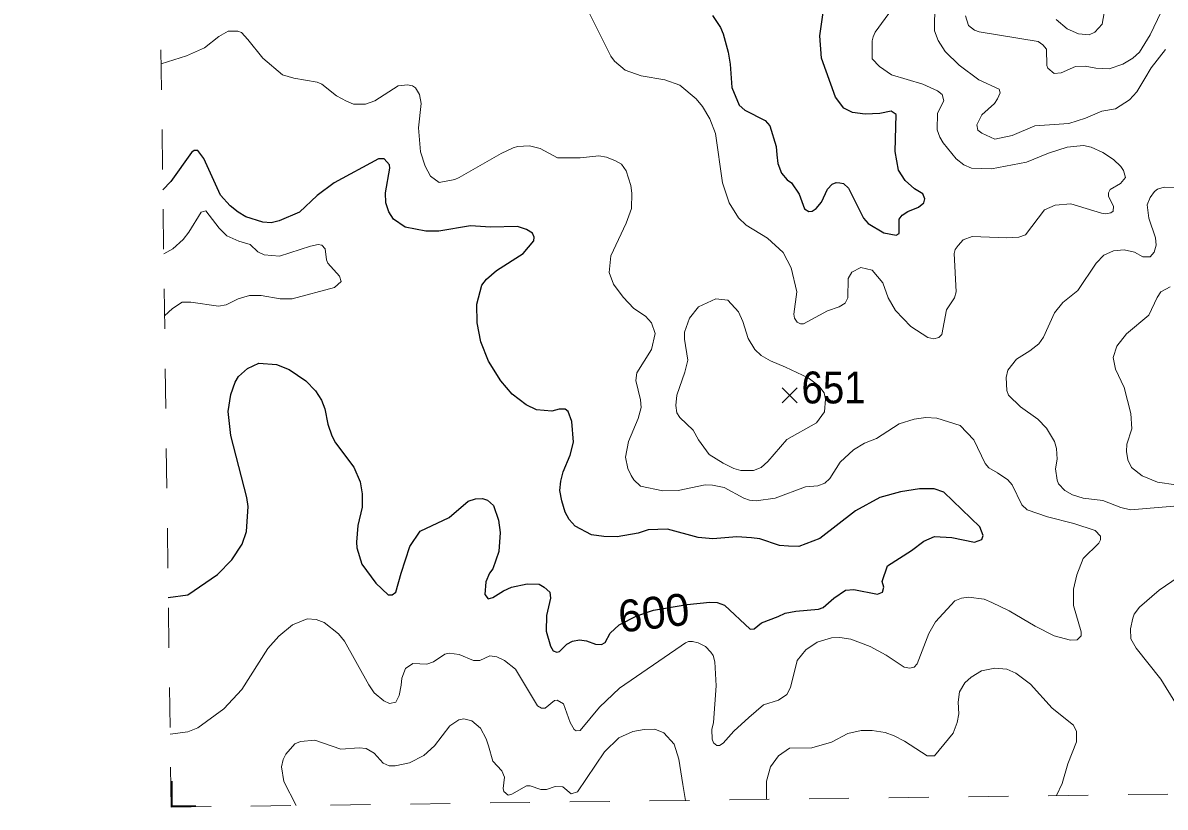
# Model space of a CAD drawing. Extents: x 294.2 to 320.3, y 7482.7 to 7510.7.
# Drawn here: x 294.252 to 297.116, y 7482.735 to 7484.703 of the extents above; entities that cross this region are included whole.
import ezdxf
from ezdxf.enums import TextEntityAlignment as Align

# ---------------------------------------------------------------- set-up
doc = ezdxf.new("R2010")
doc.units = 0
doc.header["$LTSCALE"] = 0.032
doc.linetypes.add('SHORT_DASHED', pattern=[2.7, 1.5, -1.2])
for name, color, linetype, lineweight in [('1', 7, 'Continuous', 25), ('2', 7, 'Continuous', 13), ('21', 7, 'Continuous', 25), ('22', 7, 'SHORT_DASHED', 13), ('63', 7, 'Continuous', 25)]:
    doc.layers.add(name, color=color, linetype=linetype, lineweight=lineweight)
doc.layers.add('61', color=7, linetype='Continuous')

msp = doc.modelspace()

# ---------------------------------------------------------------- linework, layer by layer
at = {"layer": '1'}
for points in [[(295.9814, 7484.7214), (296.0012, 7484.6908), (296.0076, 7484.6755), (296.0204, 7484.6295), (296.0255, 7484.5988), (296.0294, 7484.5404), (296.048, 7484.4963), (296.0619, 7484.4839), (296.1129, 7484.4575), (296.1245, 7484.4441), (296.1409, 7484.3925), (296.142, 7484.3715), (296.1451, 7484.35), (296.1542, 7484.3258), (296.1686, 7484.3093), (296.1789, 7484.3016), (296.198, 7484.2727), (296.2117, 7484.236), (296.2228, 7484.2296), (296.2308, 7484.2301), (296.2414, 7484.2371), (296.2547, 7484.2527), (296.2691, 7484.2855), (296.2813, 7484.2984), (296.2913, 7484.3027), (296.3007, 7484.3017), (296.3096, 7484.3), (296.3223, 7484.2885), (296.3594, 7484.2125), (296.3715, 7484.1997), (296.4111, 7484.1761), (296.4417, 7484.1698), (296.4488, 7484.1742), (296.4494, 7484.21), (296.4564, 7484.2202), (296.4711, 7484.2298), (296.4973, 7484.2406), (296.5113, 7484.2515), (296.5139, 7484.2611), (296.5088, 7484.2738), (296.4877, 7484.2866), (296.4641, 7484.3077), (296.4475, 7484.3332), (296.4392, 7484.3805), (296.4417, 7484.4731), (296.429, 7484.4814), (296.4009, 7484.4756), (296.3639, 7484.4737), (296.3319, 7484.4781), (296.3102, 7484.489), (296.2898, 7484.5165), (296.254, 7484.6142), (296.2502, 7484.6703), (296.2623, 7484.7521)], [(296.5375, 7483.4144), (296.5809, 7483.4119), (296.6378, 7483.4004), (296.6563, 7483.4068), (296.6601, 7483.4164), (296.6518, 7483.4387), (296.5611, 7483.5255), (296.5373, 7483.5338), (296.5006, 7483.5338), (296.4527, 7483.5263), (296.4011, 7483.5123), (296.34, 7483.4784), (296.25, 7483.4089), (296.1975, 7483.3895), (296.172, 7483.3901), (296.1493, 7483.3914), (296.0995, 7483.4087), (296.0791, 7483.4113), (296.0421, 7483.4132), (295.9821, 7483.4087), (295.945, 7483.4119), (295.8684, 7483.433), (295.8199, 7483.431), (295.7943, 7483.4228), (295.7419, 7483.4138), (295.7086, 7483.4143), (295.6773, 7483.4187), (295.6368, 7483.4402), (295.6213, 7483.4569), (295.6113, 7483.4752), (295.603, 7483.5037), (295.5985, 7483.5296), (295.601, 7483.5533), (295.6065, 7483.5764), (295.6245, 7483.6181), (295.6322, 7483.6513), (295.6283, 7483.7024), (295.6194, 7483.7279), (295.6117, 7483.7337), (295.5964, 7483.7337), (295.5785, 7483.7286), (295.5396, 7483.7318), (295.5134, 7483.7445), (295.4789, 7483.7714), (295.4502, 7483.8045), (295.4195, 7483.8544), (295.4004, 7483.9029), (295.3908, 7483.9501), (295.3902, 7483.9974), (295.4029, 7484.0446), (295.4144, 7484.06), (295.4394, 7484.0817), (295.5064, 7484.1238), (295.5326, 7484.1563), (295.5338, 7484.1653), (295.5294, 7484.1755), (295.5144, 7484.1846), (295.4922, 7484.1916), (295.4239, 7484.1906), (295.374, 7484.1938), (295.2944, 7484.1804), (295.2625, 7484.1804), (295.2104, 7484.1906), (295.1807, 7484.2105), (295.1696, 7484.2288), (295.1619, 7484.2514), (295.1613, 7484.2761), (295.1721, 7484.3379), (295.1712, 7484.3466), (295.1578, 7484.3619), (295.1437, 7484.3613), (295.0324, 7484.3011), (294.9897, 7484.2693), (294.9456, 7484.2279), (294.8946, 7484.2063), (294.8746, 7484.2015), (294.8532, 7484.2031), (294.8111, 7484.2166), (294.7911, 7484.2279), (294.7712, 7484.244), (294.7472, 7484.2706), (294.7051, 7484.3626), (294.6904, 7484.3823), (294.6808, 7484.3823), (294.6745, 7484.3773), (294.6223, 7484.3052), (294.6026, 7484.2836)], [(294.6163, 7483.261), (294.6652, 7483.2683), (294.7395, 7483.3187), (294.7753, 7483.3554), (294.8015, 7483.3947), (294.8122, 7483.4267), (294.8162, 7483.4898), (294.8136, 7483.5122), (294.7728, 7483.6679), (294.7664, 7483.728), (294.7728, 7483.7701), (294.7842, 7483.8014), (294.7926, 7483.8154), (294.8149, 7483.8358), (294.843, 7483.8493), (294.8877, 7483.8454), (294.919, 7483.8333), (294.9611, 7483.8046), (294.9853, 7483.7796), (295.0002, 7483.756), (295.0091, 7483.7345), (295.0162, 7483.6963), (295.0262, 7483.6666), (295.0352, 7483.6494), (295.0818, 7483.5881), (295.0971, 7483.5517), (295.1022, 7483.5211), (295.1022, 7483.4878), (295.0914, 7483.4419), (295.0882, 7483.3998), (295.0888, 7483.3857), (295.1016, 7483.3449), (295.1367, 7483.2976), (295.1673, 7483.2676), (295.1776, 7483.2676), (295.1871, 7483.2746), (295.1999, 7483.3219), (295.2223, 7483.3896), (295.2478, 7483.4278), (295.3207, 7483.4622), (295.3684, 7483.5031), (295.3867, 7483.5085), (295.4039, 7483.5095), (295.4172, 7483.5058), (295.4317, 7483.4918), (295.4447, 7483.4552), (295.4486, 7483.4245), (295.4451, 7483.3768), (295.4298, 7483.3333), (295.4214, 7483.3219), (295.4125, 7483.3002), (295.4105, 7483.2685), (295.4182, 7483.2583), (295.4304, 7483.261), (295.4565, 7483.2782), (295.477, 7483.2868), (295.516, 7483.2956), (295.5465, 7483.2945), (295.5587, 7483.287), (295.5731, 7483.2746), (295.5748, 7483.2596), (295.5647, 7483.2162), (295.5636, 7483.1764), (295.5747, 7483.1393), (295.5816, 7483.1275), (295.5905, 7483.1242), (295.5977, 7483.1259), (295.616, 7483.1441), (295.6299, 7483.1517), (295.6471, 7483.1554), (295.6654, 7483.1527), (295.6873, 7483.1446), (295.7023, 7483.1436), (295.7117, 7483.1484), (295.7245, 7483.1715), (295.7472, 7483.1925), (295.7913, 7483.2151), (295.8329, 7483.2291), (295.9175, 7483.2436), (295.9747, 7483.2496), (295.9925, 7483.249), (296.0114, 7483.2421), (296.0753, 7483.182), (296.0855, 7483.1827), (296.104, 7483.198), (296.1455, 7483.2139), (296.1637, 7483.2219), (296.1904, 7483.2273), (296.2469, 7483.2322), (296.2586, 7483.236), (296.2852, 7483.2596), (296.3146, 7483.2796), (296.3357, 7483.2812), (296.395, 7483.2698), (296.4072, 7483.2746)], [(296.4072, 7483.2746), (296.4105, 7483.287), (296.4067, 7483.3015), (296.42, 7483.3408), (296.4805, 7483.3789), (296.5113, 7483.4023), (296.5375, 7483.4144)]]:
    msp.add_lwpolyline(points, dxfattribs=at)
at = {"layer": '2'}
for points in [[(296.0063, 7484.3013), (296.0229, 7484.2515), (296.0459, 7484.2138), (296.0657, 7484.1953), (296.1193, 7484.1628), (296.1582, 7484.1264), (296.1787, 7484.0881), (296.1927, 7484.028), (296.185, 7483.9719), (296.1863, 7483.9616), (296.1934, 7483.9521), (296.2017, 7483.9475), (296.2093, 7483.9475), (296.2694, 7483.9801), (296.2987, 7483.9904), (296.3141, 7483.9999), (296.3204, 7484.0127), (296.3217, 7484.0612), (296.3306, 7484.0772), (296.353, 7484.0887), (296.3817, 7484.0823), (296.4085, 7484.051), (296.422, 7484.0127), (296.4404, 7483.9814), (296.4781, 7483.9412), (296.5209, 7483.9131), (296.5363, 7483.9105), (296.549, 7483.9131), (296.556, 7483.9208), (296.5675, 7483.9833), (296.588, 7484.0133), (296.5924, 7484.028), (296.5873, 7484.1238), (296.5898, 7484.134), (296.5969, 7484.1442), (296.6097, 7484.1589), (296.632, 7484.1666), (296.7189, 7484.1634), (296.7495, 7484.1653), (296.7661, 7484.171), (296.814, 7484.2336), (296.8402, 7484.2451), (296.8798, 7484.2489), (296.9564, 7484.2253), (296.9666, 7484.2234), (296.98, 7484.2259), (296.9857, 7484.2304), (296.987, 7484.2426), (296.9742, 7484.2668), (296.9742, 7484.2764), (296.9781, 7484.2847), (297.0042, 7484.2994), (297.0164, 7484.3147), (297.0119, 7484.3326), (297.0055, 7484.3428), (296.987, 7484.36), (296.9602, 7484.3779), (296.9308, 7484.3913), (296.9117, 7484.3952), (296.8708, 7484.3913), (296.8236, 7484.376), (296.7687, 7484.353), (296.6806, 7484.3364), (296.6308, 7484.3383), (296.6116, 7484.3466), (296.5918, 7484.3613), (296.5599, 7484.4022), (296.5509, 7484.4162), (296.5445, 7484.4341), (296.5452, 7484.4763), (296.5612, 7484.5075), (296.5573, 7484.5228), (296.5452, 7484.5324), (296.5082, 7484.549), (296.4303, 7484.5727), (296.3996, 7484.5937), (296.3817, 7484.6129), (296.3811, 7484.6575), (296.3843, 7484.6678), (296.3894, 7484.6793), (296.4481, 7484.761)], [(295.6596, 7484.7534), (295.726, 7484.6193), (295.7349, 7484.6071), (295.7624, 7484.5841), (295.802, 7484.5701), (295.8613, 7484.5599)], [(296.5388, 7484.7508), (296.5375, 7484.6831), (296.5471, 7484.6589), (296.5643, 7484.6308), (296.5994, 7484.5963), (296.6486, 7484.5599), (296.7003, 7484.5362), (296.7029, 7484.5273), (296.6958, 7484.512), (296.6882, 7484.5005), (296.6569, 7484.4724), (296.6442, 7484.4469), (296.6467, 7484.4335), (296.6563, 7484.4258), (296.6895, 7484.4111), (296.7329, 7484.42), (296.7891, 7484.4443), (296.8747, 7484.4507), (296.9168, 7484.4634), (296.9577, 7484.4813), (296.9921, 7484.4871), (297.0272, 7484.5094), (297.0451, 7484.5298), (297.0655, 7484.5631), (297.0809, 7484.5899), (297.1172, 7484.6358)], [(296.6154, 7484.7201), (296.623, 7484.6965), (296.6377, 7484.6843), (296.6499, 7484.6805), (296.798, 7484.6563), (296.8095, 7484.648), (296.8184, 7484.6365), (296.8197, 7484.5956), (296.8222, 7484.5892), (296.8376, 7484.5758), (296.8555, 7484.5771), (296.8913, 7484.5937), (296.9155, 7484.5944), (296.9423, 7484.5892), (296.9755, 7484.5873), (297.01, 7484.5988), (297.0355, 7484.6141), (297.0515, 7484.6295), (297.0783, 7484.6729), (297.1153, 7484.7495)], [(296.8427, 7484.7112), (296.8701, 7484.6882), (296.8989, 7484.6754), (296.9257, 7484.6729), (296.9398, 7484.6792), (296.9583, 7484.6997), (296.9634, 7484.7278)], [(294.8156, 7484.6614), (294.7996, 7484.6786), (294.7907, 7484.6818), (294.7664, 7484.6818), (294.7434, 7484.6684), (294.707, 7484.6403), (294.6617, 7484.6199), (294.5984, 7484.5999)], [(296.9538, 7483.4061), (296.9538, 7483.4151), (296.9411, 7483.4291), (296.8874, 7483.447), (296.821, 7483.4636), (296.7699, 7483.4815), (296.7565, 7483.4936), (296.7323, 7483.5441), (296.7214, 7483.5568), (296.6959, 7483.5741), (296.6741, 7483.5868), (296.6646, 7483.597), (296.6365, 7483.6564), (296.602, 7483.6928), (296.5439, 7483.7113), (296.5158, 7483.7126), (296.4865, 7483.7088), (296.4494, 7483.6973), (296.392, 7483.6602), (296.3626, 7483.6481), (296.3345, 7483.6315), (296.3013, 7483.6009), (296.2751, 7483.5594), (296.263, 7483.5479), (296.2451, 7483.5415), (296.2145, 7483.5389), (296.1378, 7483.5108), (296.0906, 7483.5038), (296.074, 7483.5051), (296.06, 7483.5102), (296.0102, 7483.5376), (295.9808, 7483.5428), (295.9629, 7483.544), (295.8952, 7483.53), (295.8569, 7483.5287), (295.8007, 7483.5409), (295.7835, 7483.5562), (295.7771, 7483.5671), (295.7688, 7483.5849), (295.7631, 7483.613), (295.7707, 7483.6526), (295.795, 7483.7101), (295.802, 7483.7382), (295.8007, 7483.7573), (295.7892, 7483.8059), (295.7917, 7483.825), (295.8282, 7483.8837), (295.8371, 7483.9233), (295.8282, 7483.9501), (295.8128, 7483.9674), (295.7835, 7483.9859), (295.7573, 7484.0146), (295.7324, 7484.0472), (295.7215, 7484.0766), (295.726, 7484.118), (295.7643, 7484.2004), (295.7777, 7484.2375), (295.779, 7484.2758), (295.7764, 7484.2949), (295.7643, 7484.332), (295.7528, 7484.3479), (295.7382, 7484.3568), (295.7152, 7484.3658), (295.696, 7484.3689), (295.6488, 7484.3638), (295.5926, 7484.3638), (295.5492, 7484.3875), (295.5224, 7484.3939), (295.4917, 7484.3926), (295.4815, 7484.3894), (295.4508, 7484.3754), (295.3461, 7484.3147), (295.3346, 7484.3096), (295.2957, 7484.3026), (295.274, 7484.3179), (295.2605, 7484.3434), (295.249, 7484.3792), (295.2439, 7484.4392), (295.2503, 7484.5005), (295.2459, 7484.5235), (295.2363, 7484.5395), (295.2286, 7484.5452), (295.2159, 7484.5471), (295.1929, 7484.5452), (295.1342, 7484.5069), (295.1112, 7484.4992), (295.0805, 7484.4986), (295.0633, 7484.5063), (295.0377, 7484.5196), (295.0014, 7484.549), (294.9899, 7484.5541), (294.9311, 7484.5637), (294.903, 7484.5726), (294.8532, 7484.6142), (294.8156, 7484.6614)], [(295.8613, 7484.5599), (295.8991, 7484.5464), (295.9399, 7484.512), (295.9559, 7484.4929), (295.9744, 7484.4622), (295.9884, 7484.4252), (296.0063, 7484.3013)], [(297.1466, 7484.2892), (297.1134, 7484.291), (297.0968, 7484.2853), (297.0898, 7484.2796), (297.0789, 7484.2643), (297.0713, 7484.2464), (297.0751, 7484.2132), (297.0917, 7484.1634), (297.0936, 7484.1455), (297.0885, 7484.1276), (297.0789, 7484.1161), (297.0604, 7484.1161), (297.0394, 7484.1276), (297.0138, 7484.1334), (296.987, 7484.1308), (296.9628, 7484.12), (296.9436, 7484.0996), (296.897, 7484.0318), (296.8593, 7484.0012), (296.8388, 7483.9757), (296.8114, 7483.9144), (296.7993, 7483.8978), (296.7769, 7483.8799), (296.7431, 7483.8595), (296.722, 7483.8314), (296.7175, 7483.8135), (296.7188, 7483.7803), (296.7233, 7483.7688), (296.7533, 7483.7394), (296.7968, 7483.7088), (296.8191, 7483.6864), (296.8388, 7483.6526), (296.844, 7483.6347), (296.8452, 7483.6079), (296.8414, 7483.5837), (296.8452, 7483.5556), (296.8491, 7483.5466), (296.8644, 7483.53), (296.8836, 7483.5185), (296.9104, 7483.5108), (296.9602, 7483.5044), (297.0049, 7483.4872), (297.0292, 7483.4815), (297.1683, 7483.493)], [(294.6048, 7484.123), (294.6278, 7484.1359), (294.6534, 7484.1596), (294.668, 7484.1774), (294.6987, 7484.2279), (294.7102, 7484.231), (294.744, 7484.1876), (294.7632, 7484.1685), (294.7932, 7484.1551), (294.8219, 7484.1468), (294.8411, 7484.1283), (294.8571, 7484.1212), (294.8954, 7484.1174), (294.9733, 7484.1429), (294.9924, 7484.1468), (295.0014, 7484.1455), (295.0097, 7484.1359), (295.0128, 7484.1085), (295.0166, 7484.0996), (295.0454, 7484.0676), (295.0498, 7484.0536), (295.0333, 7484.0389), (294.9273, 7484.0108), (294.8966, 7484.0101), (294.8494, 7484.0191), (294.82, 7484.0191), (294.7919, 7484.0108), (294.7613, 7483.9955), (294.7421, 7483.9922), (294.6732, 7484.0025), (294.6508, 7484.0019), (294.6266, 7483.9865), (294.6068, 7483.9675)], [(297.1287, 7484.0408), (297.1057, 7484.028), (297.0962, 7484.014), (297.0757, 7483.9693), (297.0189, 7483.9227), (296.9953, 7483.8914), (296.9857, 7483.8633), (296.9921, 7483.8339), (297.0138, 7483.788), (297.0304, 7483.7228), (297.0329, 7483.6845), (297.0202, 7483.6462), (297.0189, 7483.6271), (297.0227, 7483.6066), (297.0317, 7483.5874), (297.0585, 7483.5664), (297.0968, 7483.5504), (297.1428, 7483.544)], [(296.9053, 7483.175), (296.8861, 7483.2414), (296.8861, 7483.2823), (296.895, 7483.3181), (296.911, 7483.3589), (296.9499, 7483.3972), (296.9538, 7483.4061)], [(297.1645, 7483.3231), (297.1013, 7483.2797), (297.0521, 7483.237), (297.0387, 7483.2197), (297.0349, 7483.2095), (297.0291, 7483.1827), (297.0298, 7483.1572), (297.0432, 7483.1342), (297.1057, 7483.0563), (297.1434, 7482.995)], [(294.6209, 7482.9187), (294.6655, 7482.9241), (294.6904, 7482.9343), (294.7555, 7482.9816), (294.8008, 7483.0307), (294.866, 7483.1329), (294.8934, 7483.1642), (294.9279, 7483.1929), (294.9649, 7483.2076), (294.9873, 7483.2063), (295.0071, 7483.1987), (295.0429, 7483.1705), (295.0582, 7483.1521), (295.1188, 7483.0422), (295.1328, 7483.0224), (295.1571, 7483.002), (295.1712, 7482.9956), (295.1871, 7482.9988), (295.1954, 7483.0154), (295.2005, 7483.041), (295.2018, 7483.0588), (295.2114, 7483.0831), (295.2293, 7483.0958), (295.2644, 7483.0939), (295.2816, 7483.0996), (295.3097, 7483.1195), (295.3206, 7483.122), (295.3461, 7483.1182), (295.3819, 7483.1035), (295.3972, 7483.1035), (295.4228, 7483.115), (295.4406, 7483.1124), (295.4597, 7483.1029), (295.4872, 7483.0811), (295.5421, 7482.9898), (295.5523, 7482.9834), (295.5613, 7482.9834), (295.5849, 7483.0026), (295.5913, 7483.0039), (295.6073, 7482.9943), (295.6245, 7482.9477), (295.6341, 7482.9305), (295.6392, 7482.9267), (295.6488, 7482.9273), (295.6973, 7482.986), (295.7477, 7483.0339), (295.9022, 7483.1399), (295.9135, 7483.1478), (295.9211, 7483.1506), (295.9309, 7483.1512), (295.945, 7483.1476), (295.9635, 7483.138), (295.9769, 7483.124), (295.9824, 7483.116), (295.9871, 7483.0997), (295.9903, 7483.0397), (295.9833, 7482.9477), (295.9795, 7482.9299), (295.9801, 7482.9056), (295.9833, 7482.8966), (295.9923, 7482.8902), (295.9987, 7482.8902), (296.0076, 7482.896), (296.0344, 7482.926), (296.0721, 7482.9605), (296.1091, 7482.9924), (296.1468, 7483.0033), (296.1672, 7483.018), (296.1768, 7483.0358), (296.1934, 7483.1035), (296.2151, 7483.1297), (296.2438, 7483.1495), (296.2796, 7483.1603), (296.3, 7483.1609), (296.3281, 7483.1565), (296.3766, 7483.138), (296.4162, 7483.1169), (296.4615, 7483.0863), (296.4762, 7483.0837), (296.4871, 7483.0869), (296.4947, 7483.0946), (296.5234, 7483.1712), (296.54, 7483.2006), (296.5892, 7483.2529), (296.6052, 7483.2599), (296.6231, 7483.2625), (296.6627, 7483.2567), (296.6818, 7483.2491), (296.7252, 7483.228), (296.7904, 7483.189), (296.8376, 7483.1648), (296.8785, 7483.1546), (296.8957, 7483.1552), (296.9053, 7483.1654), (296.9053, 7483.175)], [(296.1162, 7482.7548), (296.1168, 7482.8009), (296.1263, 7482.8366), (296.1468, 7482.8641), (296.1742, 7482.8832), (296.2298, 7482.8838), (296.2796, 7482.8986), (296.3205, 7482.9203), (296.3537, 7482.9273), (296.3817, 7482.9273), (296.4137, 7482.9228), (296.4367, 7482.9139), (296.4628, 7482.9011), (296.5197, 7482.8641), (296.5375, 7482.8641), (296.5848, 7482.9209), (296.595, 7482.9477), (296.5988, 7482.9694), (296.5975, 7482.9988), (296.6007, 7483.0244), (296.6141, 7483.0473), (296.6295, 7483.0613), (296.6556, 7483.0773), (296.6895, 7483.0837), (296.7195, 7483.0818), (296.7418, 7483.0716), (296.7789, 7483.0435), (296.8325, 7482.9835), (296.8867, 7482.9407), (296.8938, 7482.9248), (296.8938, 7482.8992), (296.8718, 7482.844), (296.8581, 7482.7945), (296.8437, 7482.7644)], [(294.9373, 7482.7394), (294.9062, 7482.7996), (294.9004, 7482.8366), (294.9043, 7482.8551), (294.9113, 7482.8679), (294.9337, 7482.8941), (294.9477, 7482.8998), (294.9835, 7482.903), (295.0486, 7482.8807), (295.0946, 7482.8845), (295.1125, 7482.8826), (295.1322, 7482.8711), (295.1552, 7482.8456), (295.1705, 7482.8392), (295.1852, 7482.8386), (295.221, 7482.8468), (295.2568, 7482.8647), (295.2835, 7482.889), (295.3225, 7482.9394), (295.3448, 7482.9541), (295.3576, 7482.9566), (295.3774, 7482.9522), (295.3991, 7482.9337), (295.4138, 7482.9069), (295.4195, 7482.889), (295.4298, 7482.8506), (295.4528, 7482.8264), (295.4597, 7482.8104), (295.4559, 7482.7817), (295.4579, 7482.7747), (295.4687, 7482.7658), (295.4777, 7482.7676), (295.5147, 7482.7888), (295.5236, 7482.7888), (295.5504, 7482.7798), (295.5645, 7482.7798), (295.5862, 7482.7875), (295.6053, 7482.7862), (295.627, 7482.7689), (295.6424, 7482.774), (295.71, 7482.8743), (295.7464, 7482.9088), (295.7816, 7482.9254), (295.8097, 7482.9305), (295.8365, 7482.9311), (295.8588, 7482.9216), (295.885, 7482.8935), (295.8965, 7482.8558), (295.9067, 7482.792), (295.9131, 7482.7522)]]:
    msp.add_lwpolyline(points, dxfattribs=at)
msp.add_lwpolyline([(296.1643, 7483.8393), (296.1264, 7483.855), (296.1033, 7483.8684), (296.0874, 7483.8831), (296.0701, 7483.9106), (296.0574, 7483.954), (296.0465, 7483.9782), (296.0197, 7484.007), (295.989, 7484.0108), (295.9463, 7483.9904), (295.9233, 7483.9616), (295.9112, 7483.9272), (295.9112, 7483.9093), (295.9194, 7483.8569), (295.9118, 7483.8263), (295.8914, 7483.7688), (295.8895, 7483.7433), (295.892, 7483.7247), (295.899, 7483.7132), (295.9322, 7483.6807), (295.9463, 7483.6564), (295.9725, 7483.62), (296.0076, 7483.5983), (296.0344, 7483.5849), (296.0523, 7483.5798), (296.0842, 7483.5798), (296.1034, 7483.5874), (296.12, 7483.6021), (296.1678, 7483.6577), (296.2419, 7483.6998), (296.2617, 7483.7273), (296.2648, 7483.7592), (296.2609, 7483.7743), (296.2476, 7483.7921), (296.2209, 7483.812)], close=True, dxfattribs=at)
at = {"layer": '21'}
for p, q in [((296.1558, 7483.7874), (296.1933, 7483.7499)), ((296.1933, 7483.7874), (296.1558, 7483.7499))]:
    msp.add_line(p, q, dxfattribs=at)
at = {"layer": '22'}
msp.add_line((294.6234, 7482.7353), (294.2515, 7510.4214), dxfattribs=at)
msp.add_lwpolyline([(294.6234, 7482.7353), (307.2008, 7482.9), (320.3015, 7483.0604)], dxfattribs=at)
at = {"layer": '63'}
msp.add_lwpolyline([(294.6248, 7482.8006), (294.6248, 7482.739), (294.6855, 7482.739)], dxfattribs=at)

# ---------------------------------------------------------------- texts
at = {"layer": '61', "width": 0.9}
msp.add_text('651', height=0.08, dxfattribs=at).set_placement((296.2846, 7483.7481), align=Align.CENTER)
at = {"layer": '61'}
msp.add_text('600', height=0.08, rotation=6.707, dxfattribs=at).set_placement((295.8383, 7483.1834), align=Align.CENTER)

doc.saveas('drawing.dxf')
